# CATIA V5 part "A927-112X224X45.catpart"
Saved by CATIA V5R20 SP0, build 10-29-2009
Part number: A927-112X224X45
Source: Unknown
Property "A": "50.000"
Property "ARTICLENO": "A927-112X224X45"
Property "BOMINFO": "A927-112X224X45"
Property "CODE": "A927-112X224X45"
Property "CREATOR": "CADENAS GmbH"
Property "D": "18.000"
Property "D1": "26.000"
Property "F": "28.000"
Property "FORM": "A"
Property "L": "224.000"
Property "L1": "100.000"
Property "L2": "20.000"
Property "L3": "50.000"
Property "LINA": "A927-112X224X45"
Property "NB": "A927-112X224X45"
Property "NBSYN": "$CODE."
Property "NN": "A927"
Property "NT": "VDI 3387 Removable Die Heels, steel and self-lubricating"
Property "R": "25.000"
Property "S": "45.000"
Property "SUPPLIER": "CF"
Property "T": "21.000"
Property "W": "112.000"
Bounding box of the stored display mesh (mm): x -56 to 56, y 0 to 224, z -45 to 0
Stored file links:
  C:\Users\borellobunino\Desktop\3D X SITO CF\A927\GSB_OILLESS_G2290511222445\CATIAV5\A927-112X224X45.catpart
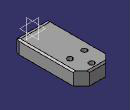
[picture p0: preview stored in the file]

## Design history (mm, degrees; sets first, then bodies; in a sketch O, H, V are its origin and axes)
Body1 "Geometry.1" (main body)
  Solid1 "A927-112X224X45.catpart": solid without history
